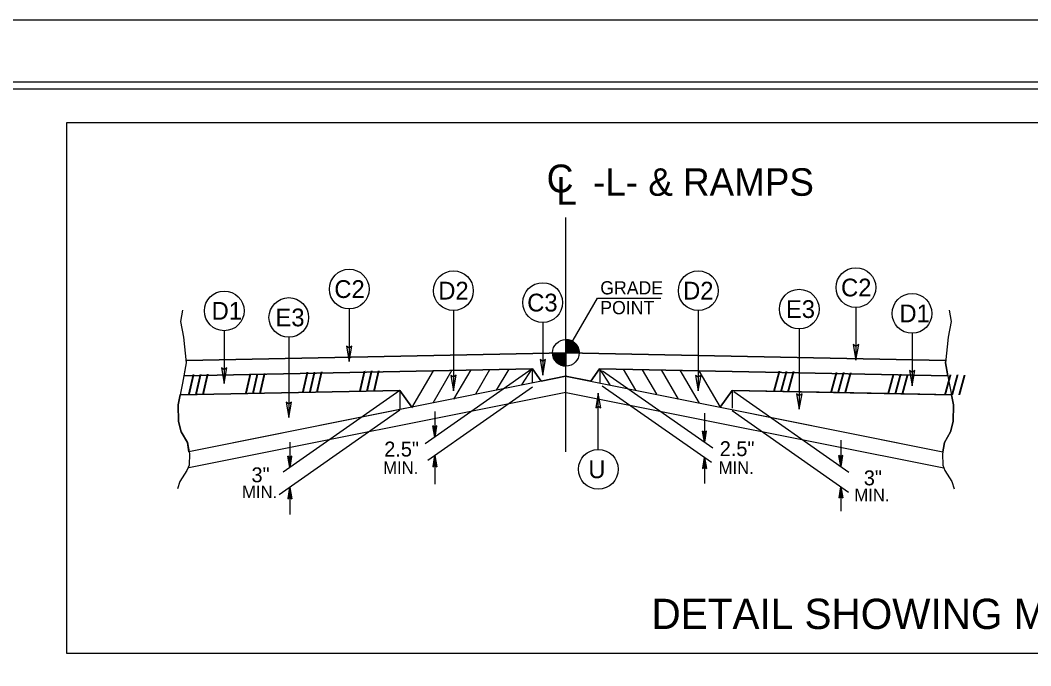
# Model space of a CAD drawing. Extents: x 573748 to 574632, y -54663 to -53209.
# Drawn here: x 574080.7 to 574154.1, y -53255.6 to -53208.7 of the extents above; entities that cross this region are included whole.
import ezdxf

# ---------------------------------------------------------------- set-up
doc = ezdxf.new("R2010")
doc.units = 0
for name, color, linetype in [('Default', 7, 'Continuous'), ('Prop Dimension', 7, 'Continuous'), ('Prop Dimension Text', 7, 'Continuous'), ('Prop Pavement Schedule Description CELL', 7, 'Continuous'), ('Prop Shade Light', 7, 'Continuous'), ('Sheet Cutting Line CELL', 7, 'Continuous'), ('Sheet Plot Border Inside CELL', 7, 'Continuous'), ('Sheet Plot Border Outside CELL', 7, 'Continuous'), ('Sheet Typical CELL', 7, 'Continuous'), ('Typical Detail Wedge2 CELL', 7, 'Continuous'), ('Typical Grade Point Symbol CELL', 7, 'Continuous'), ('Typical ID Circle CELL', 7, 'Continuous'), ('Typical Terminator CELL', 7, 'Continuous'), ('Typical Text ID Circle CELL', 7, 'Continuous')]:
    doc.layers.add(name, color=color, linetype=linetype)

msp = doc.modelspace()

# ---------------------------------------------------------------- linework, layer by layer
at = {"layer": 'Prop Dimension'}
msp.add_lwpolyline([(574120.326, -53232.878), (574122.62, -53228.895), (574127.222, -53228.895)], dxfattribs=at)
at = {"layer": 'Prop Pavement Schedule Description CELL'}
msp.add_lwpolyline([(574084.041, -53254.706), (574230.369, -53254.706), (574230.369, -53216.161), (574084.041, -53216.161)], close=True, dxfattribs=at)
at = {"layer": 'Prop Shade Light'}
for p, q in [((574120.326, -53232.878), (574092.724, -53233.429)), ((574147.93, -53233.429), (574120.326, -53232.878)), ((574092.572, -53234.538), (574117.906, -53234.032)), ((574117.906, -53234.032), (574118.525, -53234.941)), ((574122.128, -53234.941), (574122.768, -53234.032)), ((574122.768, -53234.032), (574148.082, -53234.538)), ((574147.911, -53233.605), (574147.93, -53233.429)), ((574148.082, -53234.538), (574147.911, -53233.605)), ((574118.525, -53234.941), (574120.286, -53234.574)), ((574120.286, -53234.574), (574122.128, -53234.941))]:
    msp.add_line(p, q, dxfattribs=at)
msp.add_lwpolyline([(574092.724, -53233.429), (574092.742, -53233.605), (574092.572, -53234.538)], dxfattribs=at)
at = {"layer": 'Sheet Cutting Line CELL'}
msp.add_line((574280.971, -53208.71), (573944.171, -53208.71), dxfattribs=at)
at = {"layer": 'Sheet Plot Border Inside CELL'}
msp.add_lwpolyline([(574280.071, -53213.2), (573946.771, -53213.2), (573946.771, -53424.22), (574280.071, -53424.22)], close=True, dxfattribs=at)
at = {"layer": 'Sheet Plot Border Outside CELL'}
msp.add_lwpolyline([(574280.971, -53208.71), (573944.171, -53208.71), (573944.171, -53428.71), (574280.971, -53428.71)], close=True, dxfattribs=at)
at = {"layer": 'Sheet Typical CELL'}
msp.add_lwpolyline([(574277.571, -53213.71), (573977.571, -53213.71), (573977.571, -53423.71), (574277.571, -53423.71)], close=True, dxfattribs=at)
at = {"layer": 'Typical Detail Wedge2 CELL'}
for p, q in [((574120.327, -53240.078), (574120.327, -53223.037)), ((574120.327, -53239.09), (574120.327, -53229.486)), ((574120.326, -53232.878), (574092.73, -53233.429)), ((574092.73, -53233.429), (574120.326, -53232.878)), ((574120.326, -53232.878), (574147.924, -53233.429)), ((574120.329, -53232.878), (574147.924, -53233.429)), ((574117.906, -53234.032), (574092.573, -53234.538)), ((574117.906, -53234.032), (574092.573, -53234.538)), ((574117.874, -53234.052), (574110.099, -53239.498)), ((574116.167, -53234.054), (574115.267, -53235.597)), ((574117.121, -53235.211), (574117.87, -53234.042)), ((574117.87, -53234.042), (574117.87, -53235.003)), ((574118.525, -53234.941), (574117.906, -53234.032)), ((574117.906, -53234.061), (574118.525, -53234.941)), ((574122.768, -53234.032), (574122.128, -53234.941)), ((574122.768, -53234.032), (574122.128, -53234.941)), ((574122.728, -53234.052), (574122.767, -53234.054)), ((574122.768, -53234.032), (574148.083, -53234.538)), ((574148.083, -53234.538), (574122.768, -53234.032)), ((574123.533, -53235.211), (574122.784, -53234.042)), ((574122.784, -53234.042), (574122.784, -53235.101)), ((574124.487, -53234.054), (574125.388, -53235.597)), ((574120.368, -53234.574), (574092.937, -53240.062)), ((574110.668, -53234.177), (574109.099, -53236.864)), ((574112.045, -53234.148), (574110.657, -53236.531)), ((574113.408, -53234.122), (574112.162, -53236.257)), ((574114.782, -53234.125), (574113.749, -53235.893)), ((574120.286, -53234.574), (574118.525, -53234.941)), ((574120.286, -53234.574), (574147.717, -53240.062)), ((574122.128, -53234.941), (574120.286, -53234.574)), ((574122.979, -53234.179), (574130.99, -53239.789)), ((574125.872, -53234.125), (574126.904, -53235.893)), ((574127.245, -53234.122), (574128.492, -53236.257)), ((574128.609, -53234.148), (574129.998, -53236.531)), ((574129.988, -53234.177), (574131.532, -53236.825)), ((574117.892, -53235.383), (574110.283, -53240.71)), ((574122.968, -53235.269), (574130.901, -53240.823)), ((574108.254, -53235.608), (574092.304, -53235.928)), ((574092.304, -53235.928), (574108.254, -53235.608)), ((574120.316, -53235.755), (574092.928, -53241.234)), ((574108.254, -53235.608), (574099.785, -53241.539)), ((574109.122, -53236.828), (574108.254, -53235.608)), ((574108.254, -53235.608), (574108.254, -53237)), ((574108.254, -53235.608), (574109.12, -53236.825)), ((574120.337, -53235.755), (574147.789, -53241.247)), ((574132.399, -53235.608), (574131.532, -53236.825)), ((574131.534, -53236.825), (574132.399, -53235.608)), ((574132.399, -53235.608), (574148.35, -53235.928)), ((574132.399, -53235.608), (574132.399, -53236.902)), ((574143.775, -53235.836), (574132.399, -53235.608)), ((574132.528, -53235.698), (574140.882, -53241.548)), ((574148.35, -53235.928), (574143.775, -53235.836)), ((574108.247, -53237.044), (574099.492, -53243.205)), ((574108.254, -53236.998), (574105.477, -53237.554)), ((574109.12, -53236.825), (574108.254, -53236.998)), ((574131.532, -53236.825), (574135.178, -53237.554)), ((574105.477, -53237.554), (574092.937, -53240.062)), ((574110.807, -53237.151), (574110.807, -53239.001)), ((574130.405, -53237.258), (574130.405, -53239.378)), ((574132.399, -53237.07), (574140.867, -53243.002)), ((574135.178, -53237.554), (574147.717, -53240.062)), ((574110.807, -53239.001), (574110.664, -53238.19)), ((574110.807, -53238.296), (574110.664, -53238.19)), ((574110.807, -53239.001), (574110.684, -53238.205)), ((574110.704, -53238.221), (574110.807, -53239.001)), ((574110.807, -53239.001), (574110.725, -53238.235)), ((574110.746, -53238.25), (574110.807, -53239.001)), ((574110.807, -53239.001), (574110.766, -53238.265)), ((574110.787, -53238.28), (574110.807, -53239.001)), ((574110.807, -53239.001), (574110.951, -53238.19)), ((574110.951, -53238.19), (574110.807, -53238.296)), ((574110.931, -53238.205), (574110.807, -53239.001)), ((574110.807, -53239.001), (574110.908, -53238.221)), ((574110.888, -53238.235), (574110.807, -53239.001)), ((574110.807, -53239.001), (574110.868, -53238.25)), ((574110.848, -53238.265), (574110.807, -53239.001)), ((574110.807, -53239.001), (574110.827, -53238.28)), ((574110.807, -53238.296), (574110.807, -53239.001)), ((574130.405, -53239.378), (574130.261, -53238.566)), ((574130.405, -53238.672), (574130.261, -53238.566)), ((574130.405, -53239.378), (574130.282, -53238.582)), ((574130.302, -53238.597), (574130.405, -53239.378)), ((574130.405, -53239.378), (574130.322, -53238.612)), ((574130.343, -53238.627), (574130.405, -53239.378)), ((574130.405, -53239.378), (574130.363, -53238.642)), ((574130.383, -53238.657), (574130.405, -53239.378)), ((574130.405, -53239.378), (574130.548, -53238.566)), ((574130.548, -53238.566), (574130.405, -53238.672)), ((574130.526, -53238.582), (574130.405, -53239.378)), ((574130.405, -53239.378), (574130.506, -53238.597)), ((574130.486, -53238.612), (574130.405, -53239.378)), ((574130.405, -53239.378), (574130.465, -53238.627)), ((574130.445, -53238.642), (574130.405, -53239.378)), ((574130.405, -53239.378), (574130.425, -53238.657)), ((574130.405, -53238.672), (574130.405, -53239.378)), ((574140.307, -53239.228), (574140.307, -53241.145)), ((574100.262, -53239.362), (574100.262, -53241.206)), ((574100.262, -53241.206), (574100.118, -53240.395)), ((574100.262, -53240.499), (574100.118, -53240.395)), ((574100.262, -53241.206), (574100.138, -53240.409)), ((574100.161, -53240.425), (574100.262, -53241.206)), ((574100.262, -53241.206), (574100.181, -53240.439)), ((574100.201, -53240.453), (574100.262, -53241.206)), ((574100.262, -53241.206), (574100.221, -53240.469)), ((574100.242, -53240.484), (574100.262, -53241.206)), ((574100.262, -53241.206), (574100.405, -53240.395)), ((574100.405, -53240.395), (574100.262, -53240.499)), ((574100.385, -53240.409), (574100.262, -53241.206)), ((574100.262, -53241.206), (574100.364, -53240.425)), ((574100.344, -53240.439), (574100.262, -53241.206)), ((574100.262, -53241.206), (574100.323, -53240.453)), ((574100.304, -53240.469), (574100.262, -53241.206)), ((574100.262, -53241.206), (574100.282, -53240.484)), ((574100.262, -53240.499), (574100.262, -53241.206)), ((574110.807, -53240.344), (574110.664, -53241.156)), ((574110.684, -53241.139), (574110.807, -53240.344)), ((574110.807, -53240.344), (574110.704, -53241.125)), ((574110.725, -53241.109), (574110.807, -53240.344)), ((574110.807, -53240.344), (574110.746, -53241.095)), ((574110.766, -53241.08), (574110.807, -53240.344)), ((574110.807, -53240.344), (574110.787, -53241.065)), ((574110.807, -53240.344), (574110.807, -53242.427)), ((574110.807, -53240.344), (574110.951, -53241.156)), ((574110.807, -53241.05), (574110.807, -53240.344)), ((574110.827, -53241.065), (574110.807, -53240.344)), ((574110.807, -53240.344), (574110.848, -53241.08)), ((574110.868, -53241.095), (574110.807, -53240.344)), ((574110.807, -53240.344), (574110.888, -53241.109)), ((574110.908, -53241.125), (574110.807, -53240.344)), ((574110.807, -53240.344), (574110.931, -53241.139)), ((574130.405, -53240.476), (574130.261, -53241.287)), ((574130.282, -53241.271), (574130.405, -53240.476)), ((574130.405, -53240.476), (574130.302, -53241.257)), ((574130.322, -53241.241), (574130.405, -53240.476)), ((574130.405, -53240.476), (574130.343, -53241.227)), ((574130.363, -53241.212), (574130.405, -53240.476)), ((574130.405, -53240.476), (574130.383, -53241.197)), ((574130.405, -53240.476), (574130.405, -53242.373)), ((574130.405, -53240.476), (574130.548, -53241.287)), ((574130.405, -53241.182), (574130.405, -53240.476)), ((574130.425, -53241.197), (574130.405, -53240.476)), ((574130.405, -53240.476), (574130.445, -53241.212)), ((574130.465, -53241.227), (574130.405, -53240.476)), ((574130.405, -53240.476), (574130.486, -53241.241)), ((574130.506, -53241.257), (574130.405, -53240.476)), ((574130.405, -53240.476), (574130.526, -53241.271)), ((574140.307, -53241.145), (574140.164, -53240.335)), ((574140.307, -53240.439), (574140.164, -53240.335)), ((574140.307, -53241.145), (574140.185, -53240.35)), ((574140.205, -53240.364), (574140.307, -53241.145)), ((574140.307, -53241.145), (574140.225, -53240.378)), ((574140.245, -53240.395), (574140.307, -53241.145)), ((574140.307, -53241.145), (574140.266, -53240.409)), ((574140.286, -53240.425), (574140.307, -53241.145)), ((574140.307, -53241.145), (574140.45, -53240.335)), ((574140.45, -53240.335), (574140.307, -53240.439)), ((574140.429, -53240.35), (574140.307, -53241.145)), ((574140.307, -53241.145), (574140.409, -53240.364)), ((574140.388, -53240.378), (574140.307, -53241.145)), ((574140.307, -53241.145), (574140.368, -53240.395)), ((574140.348, -53240.409), (574140.307, -53241.145)), ((574140.307, -53241.145), (574140.328, -53240.425)), ((574140.307, -53240.439), (574140.307, -53241.145)), ((574110.664, -53241.156), (574110.807, -53241.05)), ((574110.807, -53241.05), (574110.951, -53241.156)), ((574130.261, -53241.287), (574130.405, -53241.182)), ((574130.405, -53241.182), (574130.548, -53241.287)), ((574100.262, -53242.665), (574100.118, -53243.477)), ((574100.14, -53243.462), (574100.262, -53242.665)), ((574100.262, -53242.665), (574100.161, -53243.446)), ((574100.181, -53243.431), (574100.262, -53242.665)), ((574100.262, -53242.665), (574100.201, -53243.416)), ((574100.221, -53243.402), (574100.262, -53242.665)), ((574100.262, -53242.665), (574100.242, -53243.387)), ((574100.262, -53242.665), (574100.262, -53244.637)), ((574100.262, -53242.665), (574100.405, -53243.477)), ((574100.262, -53243.371), (574100.262, -53242.665)), ((574100.282, -53243.387), (574100.262, -53242.665)), ((574100.262, -53242.665), (574100.304, -53243.402)), ((574100.324, -53243.416), (574100.262, -53242.665)), ((574100.262, -53242.665), (574100.344, -53243.431)), ((574100.364, -53243.446), (574100.262, -53242.665)), ((574100.262, -53242.665), (574100.385, -53243.462)), ((574140.307, -53242.608), (574140.164, -53243.42)), ((574140.185, -53243.405), (574140.307, -53242.608)), ((574140.307, -53242.608), (574140.205, -53243.39)), ((574140.225, -53243.374), (574140.307, -53242.608)), ((574140.307, -53242.608), (574140.245, -53243.359)), ((574140.266, -53243.344), (574140.307, -53242.608)), ((574140.307, -53242.608), (574140.286, -53243.33)), ((574140.307, -53242.608), (574140.307, -53244.39)), ((574140.307, -53242.608), (574140.45, -53243.42)), ((574140.307, -53243.313), (574140.307, -53242.608)), ((574140.328, -53243.33), (574140.307, -53242.608)), ((574140.307, -53242.608), (574140.348, -53243.344)), ((574140.368, -53243.359), (574140.307, -53242.608)), ((574140.307, -53242.608), (574140.388, -53243.374)), ((574140.409, -53243.39), (574140.307, -53242.608)), ((574140.307, -53242.608), (574140.429, -53243.405)), ((574100.118, -53243.477), (574100.262, -53243.371)), ((574100.262, -53243.371), (574100.405, -53243.477)), ((574140.164, -53243.42), (574140.307, -53243.313)), ((574140.307, -53243.313), (574140.45, -53243.42))]:
    msp.add_line(p, q, dxfattribs=at)
for points in [[(574092.473, -53229.787), (574092.326, -53230.595), (574092.548, -53231.745), (574092.742, -53233.605), (574092.473, -53235.074), (574092.156, -53236.665), (574092.18, -53237.865), (574092.376, -53238.623), (574092.817, -53239.383), (574092.963, -53240.215), (574092.939, -53241.047), (574092.792, -53241.44), (574092.279, -53242.223), (574092.107, -53242.762)], [(574148.18, -53229.787), (574148.327, -53230.595), (574148.107, -53231.745), (574147.911, -53233.605), (574148.18, -53235.074), (574148.499, -53236.665), (574148.474, -53237.865), (574148.277, -53238.623), (574147.837, -53239.383), (574147.691, -53240.215), (574147.714, -53241.047), (574147.861, -53241.44), (574148.375, -53242.223), (574148.546, -53242.762)], [(574092.936, -53240.062), (574092.817, -53239.383), (574092.376, -53238.623), (574092.18, -53237.865), (574092.156, -53236.665), (574092.303, -53235.928)], [(574147.717, -53240.062), (574147.837, -53239.383), (574148.277, -53238.623), (574148.474, -53237.865), (574148.499, -53236.665), (574148.35, -53235.928)]]:
    msp.add_lwpolyline(points, dxfattribs=at)
at = {"layer": 'Typical Grade Point Symbol CELL'}
for p, q in [((574120.326, -53232.878), (574120.326, -53231.911)), ((574119.359, -53232.878), (574120.326, -53232.878)), ((574120.324, -53233.845), (574120.326, -53232.878)), ((574120.326, -53232.878), (574120.324, -53233.845)), ((574121.293, -53232.878), (574120.326, -53232.878))]:
    msp.add_line(p, q, dxfattribs=at)
for points in [[(574120.335, -53231.911), (574120.335, -53231.911), (574120.335, -53232.878)], [(574120.354, -53231.911), (574120.354, -53232.878)], [(574120.374, -53231.913), (574120.374, -53232.878)], [(574120.393, -53231.913), (574120.393, -53232.878)], [(574120.412, -53231.915), (574120.412, -53232.878)], [(574120.432, -53231.918), (574120.432, -53232.878)], [(574120.451, -53231.92), (574120.451, -53232.878)], [(574120.47, -53231.922), (574120.47, -53232.878)], [(574120.49, -53231.924), (574120.49, -53232.878)], [(574120.509, -53231.928), (574120.509, -53232.878)], [(574120.528, -53231.933), (574120.528, -53232.878)], [(574120.548, -53231.937), (574120.548, -53232.878)], [(574120.567, -53231.941), (574120.567, -53232.878)], [(574120.586, -53231.948), (574120.586, -53232.878)], [(574120.606, -53231.952), (574120.606, -53232.878)], [(574120.625, -53231.958), (574120.625, -53232.878)], [(574120.644, -53231.965), (574120.644, -53232.878)], [(574120.664, -53231.971), (574120.664, -53232.878)], [(574120.683, -53231.98), (574120.683, -53232.878)], [(574120.702, -53231.988), (574120.702, -53232.878)], [(574120.722, -53231.997), (574120.722, -53232.878)], [(574120.741, -53232.006), (574120.741, -53232.878)], [(574120.76, -53232.014), (574120.76, -53232.878)], [(574120.78, -53232.025), (574120.78, -53232.878)], [(574120.799, -53232.036), (574120.799, -53232.878)], [(574120.818, -53232.047), (574120.818, -53232.878)], [(574120.838, -53232.057), (574120.838, -53232.878)], [(574120.857, -53232.07), (574120.857, -53232.878)], [(574120.876, -53232.083), (574120.876, -53232.878)], [(574120.896, -53232.098), (574120.896, -53232.878)], [(574120.915, -53232.111), (574120.915, -53232.878)], [(574120.934, -53232.126), (574120.934, -53232.878)], [(574120.954, -53232.143), (574120.954, -53232.878)], [(574120.973, -53232.16), (574120.973, -53232.878)], [(574120.992, -53232.178), (574120.992, -53232.878)], [(574121.012, -53232.197), (574121.012, -53232.878)], [(574121.031, -53232.216), (574121.031, -53232.878)], [(574121.05, -53232.238), (574121.05, -53232.878)], [(574121.07, -53232.261), (574121.07, -53232.878)], [(574121.089, -53232.285), (574121.089, -53232.878)], [(574121.108, -53232.311), (574121.108, -53232.878)], [(574121.128, -53232.339), (574121.128, -53232.878)], [(574121.147, -53232.369), (574121.147, -53232.878)], [(574121.166, -53232.401), (574121.166, -53232.878)], [(574121.186, -53232.435), (574121.186, -53232.878)], [(574121.205, -53232.476), (574121.205, -53232.878)], [(574121.224, -53232.521), (574121.224, -53232.878)], [(574121.244, -53232.575), (574121.244, -53232.878)], [(574119.364, -53232.878), (574119.364, -53232.983)], [(574119.383, -53232.878), (574119.383, -53233.097)], [(574119.402, -53232.878), (574119.402, -53233.166)], [(574119.422, -53232.878), (574119.422, -53233.224)], [(574119.441, -53232.878), (574119.441, -53233.269)], [(574119.46, -53232.878), (574119.46, -53233.31)], [(574119.48, -53232.878), (574119.48, -53233.346)], [(574119.499, -53232.878), (574119.499, -53233.381)], [(574119.519, -53232.878), (574119.519, -53233.411)], [(574119.538, -53232.878), (574119.538, -53233.439)], [(574119.557, -53232.878), (574119.557, -53233.464)], [(574119.576, -53232.878), (574119.576, -53233.488)], [(574119.596, -53232.878), (574119.596, -53233.512)], [(574119.615, -53232.878), (574119.615, -53233.533)], [(574119.634, -53232.878), (574119.634, -53233.555)], [(574119.654, -53232.878), (574119.654, -53233.574)], [(574119.673, -53232.878), (574119.673, -53233.591)], [(574119.693, -53232.878), (574119.693, -53233.608)], [(574119.712, -53232.878), (574119.712, -53233.626)], [(574119.731, -53232.878), (574119.731, -53233.641)], [(574119.751, -53232.878), (574119.751, -53233.656)], [(574119.77, -53232.878), (574119.77, -53233.669)], [(574119.789, -53232.878), (574119.789, -53233.681)], [(574119.808, -53232.878), (574119.808, -53233.694)], [(574119.828, -53232.878), (574119.828, -53233.707)], [(574119.847, -53232.878), (574119.847, -53233.718)], [(574119.867, -53232.878), (574119.867, -53233.729)], [(574119.886, -53232.878), (574119.886, -53233.74)], [(574119.905, -53232.878), (574119.905, -53233.748)], [(574119.925, -53232.878), (574119.925, -53233.757)], [(574119.944, -53232.878), (574119.944, -53233.765)], [(574119.963, -53232.878), (574119.963, -53233.774)], [(574119.983, -53232.878), (574119.983, -53233.782)], [(574120.002, -53232.878), (574120.002, -53233.789)], [(574120.021, -53232.878), (574120.021, -53233.795)], [(574120.041, -53232.878), (574120.041, -53233.802)], [(574120.06, -53232.878), (574120.06, -53233.806)], [(574120.079, -53232.878), (574120.079, -53233.813)], [(574120.099, -53232.878), (574120.099, -53233.817)], [(574120.118, -53232.878), (574120.118, -53233.821)], [(574120.137, -53232.878), (574120.137, -53233.825)], [(574120.157, -53232.878), (574120.157, -53233.83)], [(574120.176, -53232.878), (574120.176, -53233.832)], [(574120.195, -53232.878), (574120.195, -53233.836)], [(574120.215, -53232.878), (574120.215, -53233.838)], [(574120.234, -53232.878), (574120.234, -53233.84)], [(574120.253, -53232.878), (574120.253, -53233.843)], [(574120.273, -53232.878), (574120.273, -53233.843)], [(574120.292, -53232.878), (574120.292, -53233.845)], [(574120.311, -53232.878), (574120.311, -53233.845), (574120.311, -53233.845)], [(574121.263, -53232.642), (574121.263, -53232.878)], [(574121.282, -53232.74), (574121.282, -53232.878)]]:
    msp.add_lwpolyline(points, dxfattribs=at)
msp.add_circle((574120.325, -53232.878), 0.967, dxfattribs=at)
for start, end in [(359.99048, 89.99048), (179.99048, 269.99048)]:
    msp.add_arc((574120.325, -53232.878), 0.967, start, end, dxfattribs=at)
at = {"layer": 'Typical ID Circle CELL'}
for p, q in [((574104.582, -53229.692), (574104.582, -53233.518)), ((574141.399, -53229.578), (574141.399, -53233.405)), ((574112.153, -53229.804), (574112.153, -53235.638)), ((574129.943, -53229.804), (574129.943, -53235.638)), ((574118.638, -53230.672), (574118.638, -53234.499)), ((574137.281, -53231.145), (574137.281, -53236.979)), ((574095.499, -53231.273), (574095.499, -53235.099)), ((574100.19, -53231.752), (574100.19, -53237.586)), ((574145.474, -53231.459), (574145.474, -53235.285)), ((574122.679, -53239.9), (574122.679, -53235.817))]:
    msp.add_line(p, q, dxfattribs=at)
for centre in [(574141.399, -53228.136), (574104.582, -53228.249), (574112.153, -53228.362), (574129.943, -53228.362), (574118.638, -53229.23), (574095.499, -53229.83), (574100.19, -53230.309), (574137.281, -53229.703), (574145.474, -53230.016), (574122.679, -53241.343)]:
    msp.add_circle(centre, 1.443, dxfattribs=at)
at = {"layer": 'Typical Terminator CELL'}
for points in [[(574104.388, -53232.393), (574104.582, -53233.518), (574104.782, -53232.387), (574104.582, -53232.531)], [(574141.205, -53232.28), (574141.399, -53233.405), (574141.599, -53232.274), (574141.399, -53232.417)], [(574118.445, -53233.374), (574118.638, -53234.499), (574118.838, -53233.368), (574118.638, -53233.511)], [(574095.306, -53233.974), (574095.499, -53235.099), (574095.699, -53233.968), (574095.499, -53234.112)], [(574111.959, -53234.514), (574112.153, -53235.638), (574112.353, -53234.507), (574112.153, -53234.651)], [(574129.749, -53234.514), (574129.943, -53235.638), (574130.143, -53234.507), (574129.943, -53234.651)], [(574145.28, -53234.16), (574145.474, -53235.285), (574145.674, -53234.154), (574145.474, -53234.298)], [(574122.86, -53236.871), (574122.679, -53235.817), (574122.491, -53236.877), (574122.679, -53236.742)], [(574137.088, -53235.854), (574137.281, -53236.979), (574137.481, -53235.848), (574137.281, -53235.992)], [(574099.996, -53236.461), (574100.19, -53237.586), (574100.39, -53236.455), (574100.19, -53236.599)]]:
    msp.add_lwpolyline(points, close=True, dxfattribs=at)

# ---------------------------------------------------------------- texts
at = {"layer": 'Default'}
for s, p in [('C', (574118.922, -53221.223)), ('L', (574119.62, -53222.123))]:
    msp.add_text(s, height=2.025, rotation=360, dxfattribs=at).set_placement(p)
at = {"layer": 'Prop Dimension Text'}
for s, height, rotation, p in [('-L- & RAMPS', 2, 360, (574122.297, -53221.467)), ('DETAIL SHOWING METHOD OF WEDGING', 2.2, 0, (574126.544, -53252.945))]:
    msp.add_text(s, height=height, rotation=rotation, dxfattribs=at).set_placement(p)
for s, p in [('GRADE', (574122.821, -53228.633)), ('POINT', (574122.821, -53230.073))]:
    msp.add_text(s, height=0.96, dxfattribs=at).set_placement(p)
at = {"layer": 'Typical Detail Wedge2 CELL'}
for height, rotation, p in [(1.3839, 1.14473, (574092.853, -53235.908)), (1.3839, 1.14639, (574096.989, -53235.86)), (1.3833, 1.14453, (574101.134, -53235.738)), (1.3834, 1.14629, (574105.284, -53235.653)), (1.3834, 358.85527, (574135.371, -53235.653)), (1.3834, 358.85361, (574139.52, -53235.738)), (1.3839, 358.85537, (574143.664, -53235.86)), (1.3839, 358.85371, (574147.801, -53235.908))]:
    msp.add_text('/// ', height=height, rotation=rotation, dxfattribs=at).set_placement(p)
for s, height, p in [('2.5"', 1.0817, (574107.125, -53240.413)), ('2.5"', 1.0817, (574131.502, -53240.385)), ('3"', 1.0817, (574097.481, -53242.285)), ('MIN.', 0.9039, (574107.049, -53241.672)), ('MIN.', 0.9039, (574131.426, -53241.672)), ('3"', 1.0817, (574141.973, -53242.506)), ('MIN.', 0.9039, (574096.795, -53243.438)), ('MIN.', 0.9039, (574141.287, -53243.659))]:
    msp.add_text(s, height=height, dxfattribs=at).set_placement(p)
at = {"layer": 'Typical Text ID Circle CELL'}
for s, height, p in [('C2', 1.2912, (574140.317, -53228.779)), ('C2', 1.2912, (574103.499, -53228.892)), ('D2', 1.2912, (574111.052, -53229.005)), ('D2', 1.2912, (574128.842, -53229.005)), ('C3', 1.2912, (574117.514, -53229.873)), ('D1', 1.2912, (574094.583, -53230.473)), ('E3', 1.2912, (574099.222, -53230.952)), ('E3', 1.2912, (574136.313, -53230.345)), ('D1', 1.2912, (574144.558, -53230.659)), ('U', 1.291, (574121.958, -53241.986))]:
    msp.add_text(s, height=height, dxfattribs=at).set_placement(p)

doc.saveas('drawing.dxf')
